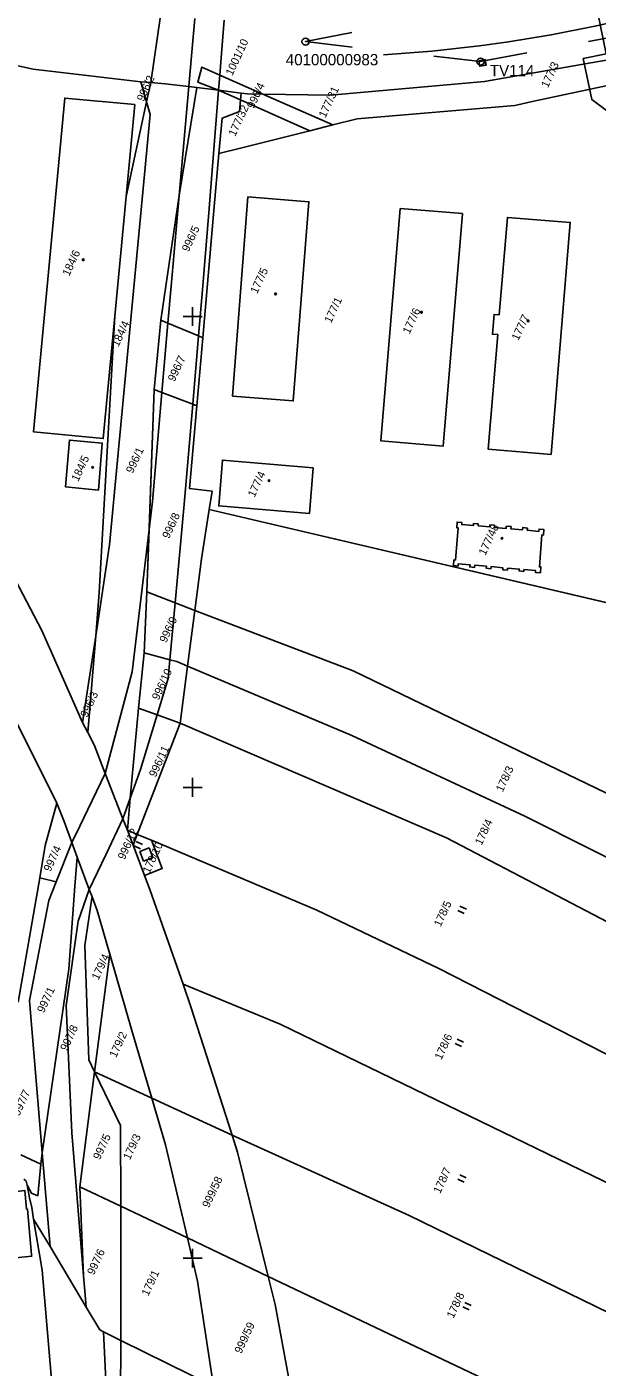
# Model space of a CAD drawing. Extents: x -755344 to -754412, y -1162670 to -1161477.
# Drawn here: x -755135.2 to -755014.1, y -1162523.1 to -1162238.5 of the extents above; entities that cross this region are included whole.
import ezdxf

# ---------------------------------------------------------------- set-up
doc = ezdxf.new("R2010")
doc.units = 0
for name, color, linetype in [('Body ŽBP', 7, 'Continuous'), ('hranice obvodu stavby', 7, 'Continuous'), ('Síť', 7, 'Continuous'), ('Vrstva 1', 7, 'Continuous'), ('Vrstva 12', 7, 'Continuous'), ('Vrstva 53', 7, 'Continuous'), ('Vrstva 55', 7, 'Continuous'), ('Vrstva 56', 7, 'Continuous'), ('Vrstva 57', 7, 'Continuous'), ('Vrstva 58', 7, 'Continuous'), ('Vrstva 59', 7, 'Continuous')]:
    doc.layers.add(name, color=color, linetype=linetype)

msp = doc.modelspace()

# ---------------------------------------------------------------- linework, layer by layer
at = {"layer": 'Body ŽBP'}
for p, q in [((-755076.02, -1162241.61), (-755066.2, -1162239.69)), ((-755006.05, -1162239.73), (-755015.88, -1162241.57)), ((-755076, -1162241.57), (-755076.03, -1162241.66)), ((-755076.02, -1162241.61), (-755076.02, -1162241.61)), ((-755076.02, -1162241.61), (-755066.08, -1162242.75)), ((-755038.84, -1162245.86), (-755048.78, -1162244.72)), ((-755038.82, -1162245.81), (-755038.86, -1162245.91)), ((-755038.84, -1162245.86), (-755029.01, -1162244.02)), ((-755038.84, -1162245.86), (-755038.84, -1162245.86))]:
    msp.add_line(p, q, dxfattribs=at)
for centre in [(-755076.02, -1162241.61), (-755038.84, -1162245.86)]:
    msp.add_circle(centre, 0.756, dxfattribs=at)
at = {"layer": 'hranice obvodu stavby'}
msp.add_lwpolyline([(-755010.64, -1162212), (-755023.37, -1162214.63), (-755020.94, -1162226.38), (-755020.94, -1162226.38), (-755020.94, -1162226.38), (-755015.16, -1162229.61), (-755012.14, -1162244.2), (-755017.04, -1162245.22), (-755015.23, -1162253.93), (-755005.62, -1162261.05)], dxfattribs=at)
at = {"layer": 'Síť'}
for points in [[(-755098, -1162300), (-755100, -1162300), (-755102, -1162300)], [(-755100, -1162298), (-755100, -1162300), (-755100, -1162302)], [(-755098, -1162400), (-755100, -1162400), (-755102, -1162400)], [(-755100, -1162398), (-755100, -1162400), (-755100, -1162402)], [(-755100, -1162498), (-755100, -1162500), (-755100, -1162502)], [(-755098, -1162500), (-755100, -1162500), (-755102, -1162500)]]:
    msp.add_lwpolyline(points, dxfattribs=at)
at = {"layer": 'Vrstva 1'}
msp.add_lwpolyline([(-755006.19, -1162236.46), (-755014.55, -1162238.36), (-755023.83, -1162240.18), (-755032.89, -1162241.66), (-755039.07, -1162242.52), (-755049.19, -1162243.63), (-755059.44, -1162244.4)], dxfattribs=at)
at = {"layer": 'Vrstva 12'}
for p, q in [((-755039.19, -1162245.66), (-755039.02, -1162246.83)), ((-755037.85, -1162245.43), (-755037.66, -1162246.64))]:
    msp.add_line(p, q, dxfattribs=at)
for points in [[(-755039.19, -1162245.66), (-755037.85, -1162245.43), (-755037.7, -1162246.63), (-755039.01, -1162246.82), (-755039.19, -1162245.66)], [(-755039.01, -1162246.82), (-755039.02, -1162246.83), (-755037.66, -1162246.64), (-755037.7, -1162246.63)]]:
    msp.add_lwpolyline(points, dxfattribs=at)
at = {"layer": 'Vrstva 53'}
msp.add_lwpolyline([(-755007.12, -1162361.91), (-755096.49, -1162341), (-755098.12, -1162351.47), (-755099.55, -1162362.44), (-755103.73, -1162360.81), (-755109.73, -1162358.47), (-755108.15, -1162315.51), (-755106.74, -1162300.78), (-755102.88, -1162274.28), (-755099.1, -1162251.37), (-755100.83, -1162251.16), (-755105.8, -1162250.54), (-755108.91, -1162250.29), (-755106.85, -1162236.16)], dxfattribs=at)
at = {"layer": 'Vrstva 55'}
for p, q in [((-755108.91, -1162250.29), (-755106.85, -1162236.16)), ((-755110.99, -1162250.12), (-755109.79, -1162254.37)), ((-755110.99, -1162250.12), (-755108.91, -1162250.29)), ((-755109.79, -1162254.37), (-755108.91, -1162250.29)), ((-755094.51, -1162251.93), (-755099.1, -1162251.37)), ((-755089.68, -1162252.52), (-755094.51, -1162251.93)), ((-755094.51, -1162251.93), (-755089.82, -1162254)), ((-755114.15, -1162274.5), (-755109.79, -1162254.37)), ((-755089.68, -1162252.52), (-755089.82, -1162254)), ((-755089.82, -1162254), (-755075.07, -1162260.52)), ((-755085.12, -1162252.75), (-755070.25, -1162259.31)), ((-755070.25, -1162259.31), (-755075.07, -1162260.52)), ((-755114.15, -1162274.5), (-755116.54, -1162299.9)), ((-755108.15, -1162315.51), (-755106.74, -1162300.78)), ((-755097.85, -1162304.49), (-755099.13, -1162318.97)), ((-755096.49, -1162341), (-755007.12, -1162361.91)), ((-755110.28, -1162371.41), (-755109.73, -1162358.47)), ((-755099.55, -1162362.44), (-755101.09, -1162374.25)), ((-755120.58, -1162367.79), (-755123.39, -1162386.22)), ((-755122.29, -1162388.33), (-755120.58, -1162367.79)), ((-755111.53, -1162383.2), (-755110.28, -1162371.41)), ((-755101.09, -1162374.25), (-755102.66, -1162386.37)), ((-755122.29, -1162388.33), (-755123.39, -1162386.22)), ((-755102.66, -1162386.37), (-755111.75, -1162409.98)), ((-755111.75, -1162409.98), (-755113.87, -1162409.08)), ((-755112.63, -1162412.26), (-755113.87, -1162409.08)), ((-755112.63, -1162412.26), (-755111.75, -1162409.98)), ((-755108.76, -1162411.24), (-755111.75, -1162409.98)), ((-755125.65, -1162411.73), (-755128.96, -1162420.05)), ((-755124.5, -1162414.82), (-755125.65, -1162411.73)), ((-755110.19, -1162418.72), (-755112.63, -1162412.26)), ((-755137.03, -1162445.6), (-755132.49, -1162419.21)), ((-755128.96, -1162420.05), (-755132.49, -1162419.21)), ((-755117.59, -1162435.42), (-755120.84, -1162460.4)), ((-755120.84, -1162460.4), (-755123.93, -1162484.86)), ((-755120.84, -1162460.4), (-755108.65, -1162466)), ((-755108.65, -1162466), (-755091.61, -1162473.83)), ((-755136.49, -1162478.06), (-755132.28, -1162480)), ((-755123.93, -1162484.86), (-755115.28, -1162488.97)), ((-755123.93, -1162484.86), (-755123.19, -1162503.76)), ((-755101.11, -1162495.7), (-755115.28, -1162488.97)), ((-755115.28, -1162488.97), (-755115.23, -1162517.45)), ((-755101.11, -1162495.7), (-755083.94, -1162503.85)), ((-754997.93, -1162544.71), (-755083.94, -1162503.85)), ((-755119.74, -1162515.24), (-755122.61, -1162510.43)), ((-755119.74, -1162515.24), (-755122.61, -1162510.43)), ((-755118.95, -1162515.63), (-755119.74, -1162515.24)), ((-755118.95, -1162515.63), (-755119.74, -1162515.24)), ((-755115.23, -1162517.45), (-755118.95, -1162515.63)), ((-755115.23, -1162517.45), (-755118.95, -1162515.63)), ((-755115.23, -1162517.45), (-755115.39, -1162536.04)), ((-755095.54, -1162527.15), (-755115.23, -1162517.45)), ((-755095.54, -1162527.15), (-755115.23, -1162517.45))]:
    msp.add_line(p, q, dxfattribs=at)
for points in [[(-755251.78, -1162217.14), (-755236.92, -1162234.12), (-755218.86, -1162255.78), (-755201.65, -1162278.82), (-755185.6, -1162302.84), (-755168.69, -1162327.53), (-755155.26, -1162350.62), (-755154.66, -1162351.82), (-755141.68, -1162377.77), (-755128.84, -1162403.34)], [(-755085.12, -1162252.75), (-755070.73, -1162253.01), (-755038.01, -1162250.05), (-755036.82, -1162249.84), (-755013.79, -1162245.86), (-755003.23, -1162244.03), (-754994.22, -1162241.55), (-754975.93, -1162236.51), (-754973.51, -1162235.29), (-754971.15, -1162234.1)], [(-754975.1, -1162243.04), (-754986.3, -1162245.44), (-755006.22, -1162249.72), (-755027.5, -1162254.28), (-755031.53, -1162255.15), (-755065.07, -1162258.01), (-755070.25, -1162259.31)], [(-755110.99, -1162250.12), (-755133.9, -1162247.44), (-755140.31, -1162246.01)], [(-755094.51, -1162251.93), (-755098.92, -1162250.25), (-755098.08, -1162247.03), (-755094.25, -1162248.72), (-755085.12, -1162252.75)], [(-755099.1, -1162251.37), (-755100.83, -1162251.16), (-755105.8, -1162250.54), (-755108.91, -1162250.29)], [(-755106.74, -1162300.78), (-755102.88, -1162274.28), (-755099.1, -1162251.37)], [(-755116.54, -1162299.9), (-755118.98, -1162325.91), (-755133.83, -1162324.47), (-755127.15, -1162253.59), (-755112.31, -1162254.97), (-755114.15, -1162274.5)], [(-755120.58, -1162367.79), (-755117.64, -1162348.46), (-755109.03, -1162257.08), (-755109.79, -1162254.37)], [(-755089.82, -1162254), (-755090.06, -1162256.44), (-755093.76, -1162257.89), (-755094.42, -1162265.37)], [(-755085.12, -1162252.75), (-755088.33, -1162252.69), (-755089.68, -1162252.52)], [(-755075.07, -1162260.52), (-755089.54, -1162264.15), (-755094.42, -1162265.37)], [(-755097.85, -1162304.49), (-755095.48, -1162277.47), (-755094.42, -1162265.37)], [(-755091.55, -1162316.9), (-755088.27, -1162274.58), (-755075.29, -1162275.61), (-755078.64, -1162317.91), (-755091.55, -1162316.9)], [(-755042.67, -1162278.13), (-755046.76, -1162327.5), (-755060.02, -1162326.4), (-755055.91, -1162277.07), (-755042.67, -1162278.13)], [(-755023.86, -1162329.29), (-755037.22, -1162328.17), (-755035.2, -1162303.84), (-755036.32, -1162303.75), (-755035.98, -1162299.54), (-755034.86, -1162299.63), (-755033.14, -1162278.93), (-755019.78, -1162280.01), (-755023.86, -1162329.29)], [(-755120.58, -1162367.79), (-755119.82, -1162358.61), (-755116.54, -1162299.9)], [(-755106.74, -1162300.78), (-755105.27, -1162301.39), (-755098.74, -1162304.12), (-755097.85, -1162304.49)], [(-755109.73, -1162358.47), (-755109.24, -1162345.2), (-755108.15, -1162315.51)], [(-755108.15, -1162315.51), (-755106.54, -1162316.13), (-755099.98, -1162318.64), (-755099.13, -1162318.97)], [(-755099.13, -1162318.97), (-755100.67, -1162336.51), (-755095.88, -1162337.08), (-755096.49, -1162341)], [(-755152.98, -1162327.62), (-755143.37, -1162345.14), (-755132.01, -1162366.71), (-755123.39, -1162386.22)], [(-755120.03, -1162336.84), (-755127.02, -1162336.14), (-755126.17, -1162326.23), (-755119.21, -1162326.86), (-755120.03, -1162336.84)], [(-755075.18, -1162341.85), (-755094.45, -1162340.23), (-755093.69, -1162330.47), (-755074.4, -1162332.14), (-755075.18, -1162341.85)], [(-755096.49, -1162341), (-755098.12, -1162351.47), (-755099.55, -1162362.44)], [(-755039.37, -1162344.47), (-755036.88, -1162344.68), (-755036.85, -1162344.25), (-755035.85, -1162344.33), (-755035.89, -1162344.78), (-755033.4, -1162344.99), (-755033.37, -1162344.54), (-755032.37, -1162344.62), (-755032.41, -1162345.07), (-755029.93, -1162345.31), (-755029.89, -1162344.83), (-755028.89, -1162344.92), (-755028.93, -1162345.39), (-755026.45, -1162345.62), (-755026.4, -1162345.13), (-755025.41, -1162345.21), (-755025.5, -1162346.41), (-755025.8, -1162346.38), (-755026.33, -1162353.16), (-755026.03, -1162353.18), (-755026.13, -1162354.41), (-755027.17, -1162354.33), (-755027.14, -1162353.95), (-755029.63, -1162353.74), (-755029.66, -1162354.12), (-755030.66, -1162354.04), (-755030.62, -1162353.64), (-755033.11, -1162353.44), (-755033.15, -1162353.84), (-755034.14, -1162353.76), (-755034.11, -1162353.34), (-755036.6, -1162353.11), (-755036.64, -1162353.55), (-755037.63, -1162353.47), (-755037.6, -1162353.02), (-755040.09, -1162352.82), (-755040.12, -1162353.27), (-755041.12, -1162353.19), (-755041.08, -1162352.7), (-755043.57, -1162352.49), (-755043.61, -1162352.98), (-755044.61, -1162352.9), (-755044.51, -1162351.69), (-755044.19, -1162351.72), (-755043.59, -1162344.89), (-755043.91, -1162344.86), (-755043.81, -1162343.66), (-755042.82, -1162343.74), (-755042.85, -1162344.19), (-755040.37, -1162344.39), (-755040.33, -1162343.95), (-755039.33, -1162344.04), (-755039.37, -1162344.47)], [(-755109.73, -1162358.47), (-755103.73, -1162360.81), (-755099.55, -1162362.44)], [(-755099.55, -1162362.44), (-755065.93, -1162375.26), (-755012.09, -1162401.26), (-754952.51, -1162431.09)], [(-755110.28, -1162371.41), (-755104.84, -1162372.89), (-755103.37, -1162373.29), (-755101.09, -1162374.25)], [(-755101.09, -1162374.25), (-755066.17, -1162388.99), (-755029.41, -1162406.11), (-754957.02, -1162442.51)], [(-755113.87, -1162409.08), (-755113.26, -1162402.31), (-755111.53, -1162383.2)], [(-755111.53, -1162383.2), (-755107.56, -1162384.62), (-755102.66, -1162386.37)], [(-755122.29, -1162388.33), (-755120.94, -1162390.93), (-755118.55, -1162397.08), (-755114.81, -1162406.67), (-755113.87, -1162409.08)], [(-755102.66, -1162386.37), (-755046.04, -1162410.7), (-754989.82, -1162440.1), (-754962.03, -1162455.19)], [(-755132.49, -1162419.21), (-755131.31, -1162412.32), (-755128.84, -1162403.34)], [(-755128.84, -1162403.34), (-755127.32, -1162407.23), (-755125.65, -1162411.73)], [(-755110.19, -1162418.72), (-755106.46, -1162417.25), (-755108.76, -1162411.24)], [(-755108.76, -1162411.24), (-755073.63, -1162426.1), (-755047.73, -1162438.47), (-754970.94, -1162477.7)], [(-755132.28, -1162480), (-755131.94, -1162477.65), (-755126.31, -1162438.59), (-755125.01, -1162420.99), (-755124.5, -1162414.82)], [(-755121.35, -1162423.28), (-755121.95, -1162421.66), (-755124.5, -1162414.82)], [(-755110.19, -1162418.72), (-755109.07, -1162421.69), (-755102.04, -1162441.81)], [(-755121.35, -1162423.28), (-755121.39, -1162423.55), (-755122.9, -1162433.61), (-755122.06, -1162457.89), (-755120.84, -1162460.4)], [(-755121.35, -1162423.28), (-755120.28, -1162426.16), (-755117.59, -1162435.42)], [(-755117.59, -1162435.42), (-755112.89, -1162451.61), (-755108.65, -1162466)], [(-755102.04, -1162441.81), (-755081.44, -1162450.28), (-754979.63, -1162499.65)], [(-755102.04, -1162441.81), (-755100.37, -1162446.59), (-755091.61, -1162473.83)], [(-755120.84, -1162460.4), (-755115.31, -1162471.78), (-755115.28, -1162488.97)], [(-755101.11, -1162495.7), (-755105.74, -1162475.9), (-755108.65, -1162466)], [(-755083.94, -1162503.85), (-755090.44, -1162477.46), (-755091.61, -1162473.83)], [(-755091.61, -1162473.83), (-755054.02, -1162490.91), (-754988.9, -1162522.63)], [(-755135.17, -1162484.49), (-755134.2, -1162486.2), (-755132.85, -1162486.73), (-755132.28, -1162480)], [(-755135.17, -1162484.49), (-755135.35, -1162483.65), (-755135.89, -1162483.24)], [(-755135.17, -1162484.49), (-755135.35, -1162483.65), (-755135.89, -1162483.24)], [(-755133.78, -1162491.69), (-755134.18, -1162489.26), (-755134.62, -1162487.15), (-755135.17, -1162484.49)], [(-755133.78, -1162491.69), (-755134.18, -1162489.26), (-755134.62, -1162487.15), (-755135.17, -1162484.49)], [(-755135.28, -1162489.58), (-755135.65, -1162485.61), (-755141.54, -1162486.3), (-755146.99, -1162486.73), (-755146.57, -1162490.74), (-755154.79, -1162491.58), (-755158.29, -1162491.94), (-755157.33, -1162501.33), (-755153.82, -1162500.97), (-755153.76, -1162501.54), (-755134.18, -1162499.57), (-755134.2, -1162499.29), (-755135.1, -1162489.56), (-755135.28, -1162489.58)], [(-755122.61, -1162510.43), (-755130.29, -1162497.54), (-755133.78, -1162491.69)], [(-755128.8, -1162539.82), (-755131.98, -1162502.55), (-755133.78, -1162491.69)], [(-755122.61, -1162510.43), (-755130.29, -1162497.54), (-755133.78, -1162491.69)], [(-755095.54, -1162527.15), (-755098.96, -1162504.9), (-755101.11, -1162495.7)], [(-755123.19, -1162503.76), (-755122.83, -1162507.8), (-755122.61, -1162510.43)], [(-755083.94, -1162503.85), (-755082.47, -1162509.84), (-755077.64, -1162535.97)], [(-755117.62, -1162544.13), (-755117.62, -1162543.52), (-755118.95, -1162515.63)]]:
    msp.add_lwpolyline(points, dxfattribs=at)
at = {"layer": 'Vrstva 56'}
for p, q in [((-755099.55, -1162236.71), (-755100.18, -1162243.88)), ((-755093.88, -1162244.12), (-755093.31, -1162237.02)), ((-755100.18, -1162243.88), (-755100.83, -1162251.16)), ((-755094.25, -1162248.72), (-755093.88, -1162244.12)), ((-755094.51, -1162251.93), (-755094.25, -1162248.72)), ((-755100.83, -1162251.16), (-755102.88, -1162274.28)), ((-755096.52, -1162277.02), (-755094.51, -1162251.93)), ((-755102.88, -1162274.28), (-755104.59, -1162293.54)), ((-755097.9, -1162294.33), (-755096.52, -1162277.02)), ((-755105.27, -1162301.39), (-755104.59, -1162293.54)), ((-755097.9, -1162294.33), (-755098.74, -1162304.12)), ((-755106.54, -1162316.13), (-755105.27, -1162301.39)), ((-755098.74, -1162304.12), (-755099.98, -1162318.64)), ((-755108.54, -1162339.27), (-755106.54, -1162316.13)), ((-755099.98, -1162318.64), (-755101.79, -1162339.87)), ((-755109.24, -1162345.2), (-755108.54, -1162339.27)), ((-755101.79, -1162339.87), (-755103.73, -1162360.81)), ((-755112.82, -1162375.43), (-755109.24, -1162345.2)), ((-755103.73, -1162360.81), (-755104.84, -1162372.89)), ((-755104.84, -1162372.89), (-755105.21, -1162376.88)), ((-755118.55, -1162397.08), (-755112.82, -1162375.43)), ((-755105.21, -1162376.88), (-755107.56, -1162384.62)), ((-755107.56, -1162384.62), (-755111.08, -1162396.2)), ((-755118.55, -1162397.08), (-755122.24, -1162404.71)), ((-755111.08, -1162396.2), (-755113.26, -1162402.31)), ((-755113.26, -1162402.31), (-755114.81, -1162406.67)), ((-755122.24, -1162404.71), (-755123.95, -1162408.22)), ((-755123.95, -1162408.22), (-755125.65, -1162411.73)), ((-755118.44, -1162414.3), (-755114.81, -1162406.67)), ((-755121.95, -1162421.66), (-755118.44, -1162414.3)), ((-755109.24, -1162412.85), (-755111.25, -1162413.65)), ((-755111.25, -1162413.65), (-755110.44, -1162415.65)), ((-755108.45, -1162414.86), (-755109.24, -1162412.85)), ((-755110.44, -1162415.65), (-755108.45, -1162414.86)), ((-755128.96, -1162420.05), (-755130.55, -1162424.05)), ((-755124.28, -1162428.44), (-755121.95, -1162421.66)), ((-755130.55, -1162424.05), (-755134.62, -1162445.29)), ((-755126.85, -1162446.31), (-755124.28, -1162428.44)), ((-755134.62, -1162445.29), (-755131.94, -1162477.65)), ((-755125.67, -1162473.35), (-755126.85, -1162446.31)), ((-755123.19, -1162503.76), (-755125.67, -1162473.35)), ((-755131.94, -1162477.65), (-755131.67, -1162480.93)), ((-755131.67, -1162480.93), (-755130.29, -1162497.54))]:
    msp.add_line(p, q, dxfattribs=at)
at = {"layer": 'Vrstva 58'}
for p, q in [((-755110.64, -1162412.16), (-755112, -1162411.52)), ((-755111.07, -1162413.06), (-755112.43, -1162412.43)), ((-755041.86, -1162425.86), (-755043.22, -1162425.22)), ((-755042.29, -1162426.76), (-755043.65, -1162426.13)), ((-755042.45, -1162454.14), (-755043.81, -1162453.5)), ((-755042.88, -1162455.04), (-755044.24, -1162454.41)), ((-755041.89, -1162482.96), (-755043.25, -1162482.32)), ((-755042.32, -1162483.86), (-755043.68, -1162483.23)), ((-755041.26, -1162510.96), (-755042.62, -1162510.33)), ((-755040.83, -1162510.06), (-755042.19, -1162509.42))]:
    msp.add_line(p, q, dxfattribs=at)
at = {"layer": 'Vrstva 59'}
for centre in [(-755123.25, -1162287.94), (-755082.39, -1162295.18), (-755051.39, -1162299.07), (-755028.73, -1162300.92), (-755121.25, -1162332.01), (-755083.79, -1162334.87), (-755034.29, -1162347.11)]:
    msp.add_circle(centre, 0.175, dxfattribs=at)

# ---------------------------------------------------------------- texts
at = {"layer": 'Body ŽBP'}
for s, p in [(' 40100000983', (-755081.1, -1162246.64)), (' TV114', (-755037.75, -1162248.95))]:
    msp.add_text(s, height=2.4, dxfattribs=at).set_placement(p)
at = {"layer": 'Vrstva 57'}
for s, p in [('1001/10', (-755091.56, -1162248.97)), ('177/3', (-755024.54, -1162251.56)), ('996/2', (-755110.43, -1162254.46)), ('996/4', (-755087.02, -1162255.98)), ('177/31', (-755071.79, -1162257.93)), ('177/32', (-755090.97, -1162261.87)), ('996/5', (-755100.86, -1162286.38)), ('184/6', (-755126.23, -1162291.54)), ('177/5', (-755086.31, -1162295.29)), ('177/1', (-755070.59, -1162301.53)), ('177/6', (-755053.94, -1162303.84)), ('177/7', (-755030.81, -1162305.23)), ('184/4', (-755115.77, -1162306.57)), ('996/7', (-755103.84, -1162313.94)), ('996/1', (-755112.72, -1162333.43)), ('184/5', (-755124.31, -1162335.16)), ('177/4', (-755086.85, -1162338.52)), ('996/8', (-755105.03, -1162347.31)), ('177/48', (-755037.83, -1162350.87)), ('996/9', (-755105.61, -1162369.42)), ('996/10', (-755107.23, -1162381.6)), ('996/3', (-755122.41, -1162385.29)), ('996/11', (-755107.84, -1162397.97)), ('178/3', (-755034.15, -1162401.12)), ('178/4', (-755038.61, -1162412.41)), ('996/12', (-755114.47, -1162415.5)), ('997/4', (-755130.23, -1162418.05)), ('178/10', (-755109.18, -1162418.42)), ('178/5', (-755047.33, -1162429.75)), ('179/4', (-755120.01, -1162441.03)), ('997/1', (-755131.61, -1162448.03)), ('997/8', (-755126.69, -1162456.11)), ('179/2', (-755116.27, -1162457.54)), ('178/6', (-755047.17, -1162458)), ('997/7', (-755136.83, -1162469.89)), ('997/5', (-755119.71, -1162479.23)), ('179/3', (-755113.33, -1162479.26)), ('999/58', (-755096.53, -1162489.44)), ('178/7', (-755047.43, -1162486.4)), ('997/6', (-755120.98, -1162503.7)), ('179/1', (-755109.42, -1162508.17)), ('178/8', (-755044.6, -1162512.9)), ('999/59', (-755089.68, -1162520.39))]:
    msp.add_text(s, height=1.7, rotation=65, dxfattribs=at).set_placement(p)

doc.saveas('drawing.dxf')
